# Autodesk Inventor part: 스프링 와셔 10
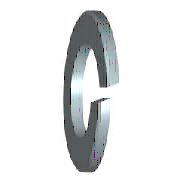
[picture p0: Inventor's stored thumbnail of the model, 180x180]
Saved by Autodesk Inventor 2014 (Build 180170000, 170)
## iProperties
Created: 2012-02
Part Number: 스프링 와셔 10
Material: 강철, 연강
Description: 스프링 잠금 와셔
Document SubType Name: Modeling
Standard: KS B 1324
Designer: mduedu
Standards Organization: KS
Language: ko-KR
Size Designation: 번호 2 - 10
Categories: <MemberInstance><Categories><Category DisplayName="조임쇠" InternalName="e4da775c-781d-43d5-af7c-5136215cf5a6" Mnemonic="FSTN"><Category DisplayName="와셔" InternalN
Density: 1 g/cm^3
Appearance: Steel
IsCustomPart: 1
Author: mduedu
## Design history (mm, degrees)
sketch "스케치1"
  geometry: C1 r 8.8 at (0, 0); C2 r 5.1 at (0, 0); 1 further point
  constraints: 2 centre point, 2 coincident
  dimensions: "d0" = 10.2 diameter of C2 (= SD1); "d1" = 17.6 diameter of C1 (= SD2)
extrude "본체" new body sketch "스케치1" distance "d2" = 2.5 (= SD); taper "d3" = 0 deg
sketch "스케치2"
  geometry: L1 (0, -5.1)-(0, 5.1) reference; L2 (2.5, 8.8)-(2.5, -8.8) reference; L3 (-1.2, 0)-(7.2, 0) reference; L4 (0, -0.5)-(2.5, 0.41); L5 (0, 0.5)-(2.5, 1.41)
  constraints: 4 end point, 4 point on line, 1 parallel
  dimensions: "d4" = 0.5 distance from line of L3 L4.start (= 0.2 x SD); "d5" = 0.5 distance from line of L3 L5.start (= 0.2 x SD); "d6" = 70 deg angle of L2 L4 (= FAWI)
extrude "절단부" cut sketch "스케치2" stored distance "d7" = 2.5 (= SD); taper "d8" = 0 deg
workaxis "Work Axis1"
workplane "Work Plane1"
body "Solid1"
other parameters: "SD1" = 10.2 [user parameter; used in 1 equation term], "SD2" = 17.6 [user parameter; used in 1 equation term], "SD" = 2.5 [user parameter; used in 4 equation terms], "FAWI" = 70 deg [user parameter; used in 1 equation term], "d9" = 0, "d10" = 0, "d11" = 0, "d12" = 0, "SDI" = 3.7 [user parameter]
